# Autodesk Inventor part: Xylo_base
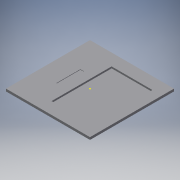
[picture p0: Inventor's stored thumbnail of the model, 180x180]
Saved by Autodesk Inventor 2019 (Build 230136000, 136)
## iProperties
Created: 2020-02
Part Number: Xylo_base
Material: Generic
Document SubType Name: Modeling
Designer: Bharath
Density: 1 g/cm^3
Appearance: Default
Author: Bharath
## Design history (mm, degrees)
sketch "Sketch1"
  geometry: L1 (-175, -175)-(175, -175); L2 (175, -175)-(175, 175); L3 (175, 175)-(-175, 175); L4 (-175, 175)-(-175, -175); L5 (-175, -175)-(175, 175); L6 (175, -175)-(-175, 175); L7 (115, -50)-(100, -50); L8 (100, -50)-(100, 50); L9 (100, 50)-(115, 50); L10 (115, 50)-(115, -50); 1 further point
  constraints: 20 end point, 4 parallel, 2 horizontal, 2 midpoint, 2 perpendicular
  dimensions: "d0" = 350 distance of L3.end L2.end; "d1" = 350 distance of L2.end L1.end; "d10" = 15 distance of L8.end L9.end; "d11" = 100 distance of L9.end L7.start; "d12" = 125 distance between parallel lines of L1 L7; "d13" = 60 distance between parallel lines of L2 L10
extrude "Extrusion1" new body sketch "Sketch1" distance "d2" = 10; taper "d3" = 0 deg
sketch "Sketch2"
  geometry: 1 further point
sketch "Sketch3"
  geometry: L1 (135, 125)-(-35, 125); L2 (-35, 125)-(-35, -125); L3 (-35, -125)-(135, -125); L4 (135, -125)-(135, 125); L5 (135, 125)-(-35, -125); L6 (-35, 125)-(135, -125); L7 (-175, -175)-(175, -175) reference; L8 (175, -175)-(175, 175) reference; 2 further points
  constraints: 12 end point, 2 midpoint, 2 parallel, 1 horizontal, 1 perpendicular
  dimensions: "d4" = 170 distance of L3.end L2.end; "d5" = 250 distance of L2.end L1.end; "d6" = 50 distance between parallel lines of L7 L3; "d7" = 40 distance between parallel lines of L8 L4
extrude "Extrusion2" cut sketch "Sketch3" distance "d8" = 7; taper "d9" = 0 deg
sketch "Sketch4"
  geometry: L1 (-90, -50)-(-75, -50); L2 (-75, -50)-(-75, 50); L3 (-75, 50)-(-90, 50); L4 (-90, 50)-(-90, -50); L5 (-175, -175)-(175, -175) reference; L6 (-35, -125)-(-35, 125) reference; 1 further point
  constraints: 8 end point, 2 parallel, 1 horizontal, 1 perpendicular
  dimensions: "d14" = 15 distance of L3.end L2.end; "d15" = 100 distance of L1.end L2.end; "d16" = 125 distance from line of L5 L1.end; "d17" = 40 distance between parallel lines of L2 L6
extrude "Extrusion3" cut sketch "Sketch4" distance "d18" = 2; taper "d19" = 0 deg
body "Solid1"
